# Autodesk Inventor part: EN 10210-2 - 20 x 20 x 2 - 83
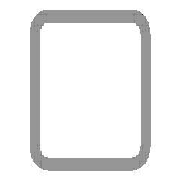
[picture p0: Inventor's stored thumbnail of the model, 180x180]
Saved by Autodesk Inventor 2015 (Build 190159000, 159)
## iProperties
Created: 2015-05
Part Number: EN 10210-2 - 20 x 20 x 2 - 83
Material: Steel, Mild
Description: Tube
Document SubType Name: Modeling
Standard: DIN
Designer: TREINA6
Standard Revision: 1997
Standards Organization: DIN
Language: en-US
Size Designation: 20 x 20 x 2
Categories: <MemberInstance><Categories><Category DisplayName="Structural Shapes" InternalName="089c4875-fa83-4c05-b084-43b9cc11f5ed" Mnemonic="GRDR"><CategoryParameter Dis
Stock Number: 20 x 20 x 2
Density: 7.85 g/cm^3
Appearance: Semi-Polished
IsCustomPart: 1
_CCFamilyMember: 1
_CCFamilyDisplayName: DIN EN 10210-2 (Square) - Tube
_FrameMemberDoc: Frame Member File
_Version: 15.0.0
_GetPNFromCC: 1
Author: TREINA6
G_L: 83,000 mm
G_W: 20,000 mm
G_H: 20,000 mm
+2FDBA401-B192-4F64-A1FE-3CD85CBC4426+CUTDETAIL1: Cut
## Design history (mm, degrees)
node "Start plane"
node "End plane"
sketch "Sketch"
  geometry: L1 (-10, -7)-(-10, 7); L2 (-7, 10)-(7, 10); L3 (10, 7)-(10, -7); L4 (7, -10)-(-7, -10); L5 (-7, 8)-(7, 8); L6 (8, 7)-(8, -7); L7 (7, -8)-(-7, -8); L8 (-8, -7)-(-8, 7); L9 (0, 14.87)-(0, -14.87) reference; L10 (-14.87, 0)-(14.87, 0) reference; A1 r 3 centre (-7, -7) between (-10, -7) and (-7, -10); A2 r 3 centre (-7, 7) between (-7, 10) and (-10, 7); A3 r 3 centre (7, 7) between (10, 7) and (7, 10); A4 r 3 centre (7, -7) between (7, -10) and (10, -7); A5 r 1 centre (-7, 7) between (-7, 8) and (-8, 7); A6 r 1 centre (7, 7) between (8, 7) and (7, 8); A7 r 1 centre (7, -7) between (7, -8) and (8, -7); A8 r 1 centre (-7, -7) between (-8, -7) and (-7, -8)
  constraints: 16 end point, 16 point on circle, 8 centre point, 8 tangent, 4 parallel, 3 equal radius, 2 perpendicular, 7 other
  dimensions: "d7" = 3 radius of A1 (= G_IR); "d10" = 20 distance between parallel lines of L2 L4 (= G_H); "d11" = 20 distance between parallel lines of L1 L3 (= G_W); "d12" = 2 distance between parallel lines of L3 L6 (= G_T); "d15" = 10 distance between parallel lines of L2 L10 (= 0.5 x d10); "d16" = 10 distance between parallel lines of L9 L3 (= 0.5 x d11)
extrude "Body" new body sketch "Sketch" stored distance "d3" = 83 (= G_L); taper "d4" = 0 deg
node "Driven Length"
  sketch "Sketch3"
    geometry: L1 (0, 0)-(10, 0) reference
    constraints: 2 end point, 1 horizontal
  workplane "Work Plane3"
  sketch "Sketch4"
    geometry: L1 (-2, 20)-(12, 20) reference; L2 (-2, 103)-(12, 103) reference
    dimensions: "d18" = 83 distance between parallel lines of L1 L2 (derived)
workplane "Work Plane4"
split "Split1"
body "Solid1"
other parameters: "G_W" = 20 [user parameter; used in 1 equation term], "G_H" = 20 [user parameter; used in 1 equation term], "G_T" = 2 [user parameter; used in 1 equation term], "G_IR" = 3 [user parameter; used in 1 equation term], "G_L" = 83 (= d18) [user parameter; used in 1 equation term], "G_OFFSET_END" = 0 [user parameter; used in 1 equation term], "d14" = 103 (= G_OFFSET_END + B_L), "B_L" = 103 [user parameter; used in 1 equation term], "d17" = 90 deg
